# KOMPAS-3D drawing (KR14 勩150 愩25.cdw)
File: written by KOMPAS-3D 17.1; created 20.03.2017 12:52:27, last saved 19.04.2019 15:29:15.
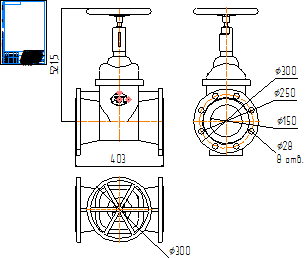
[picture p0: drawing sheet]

Sheet 1: A4, portrait

Title block, sheet 1: name: KR14 Ду150 Ру25; material: Внимание! Данный продукт является объектом авторского права ООО «Торговый Дом АДЛ». / Запрещается изменение, копирование, распространение / (в том числе путем копирования на другие сайты и ресурсы в Интернете) / или любое иное использование информации и объектов без предварительного / согласия правообладателя (ООО «Торговый Дом АДЛ»).; mass: 508; sheets: 1; organisation: ООО "Торговый дом АДЛ"; sheet format: A4; stored path: C:\Users\kka\KOMPAS_Work\!Trash\Задвижки ГРАНАР с приводами\KR14 Ду350 Ру16.cdw

Views: Вид 1, Проекционный вид 2, Проекционный вид 3
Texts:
  Klimkovich
  ADL
Dimensions and other numbers on the sheet: 521,5; 403; 300; 250; 28; 8 отв.; 150; 1:1; 1; 508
